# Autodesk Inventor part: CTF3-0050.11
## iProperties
Shininess: 64.0
Length Units: 11269
Angle Units: 11279
Time Units: 11290
Mass Units: 11283
Length Display Precision: 3
Angle Display Precision: 2
Compacted: True
Part Number: CTF3-0050.11
Document SubType Name: Modeling
Created: 2003-12
Designer: Lollo
Density: 0.0
Volumn: 0.0
Area: 0.0
PropertySet Name: Model Information
Control State: 0
Master: False
Checked Out: False
Author: Lollo
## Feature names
1. Estrusione1 [Extrusion]
2. Estrusione2 [Extrusion]
